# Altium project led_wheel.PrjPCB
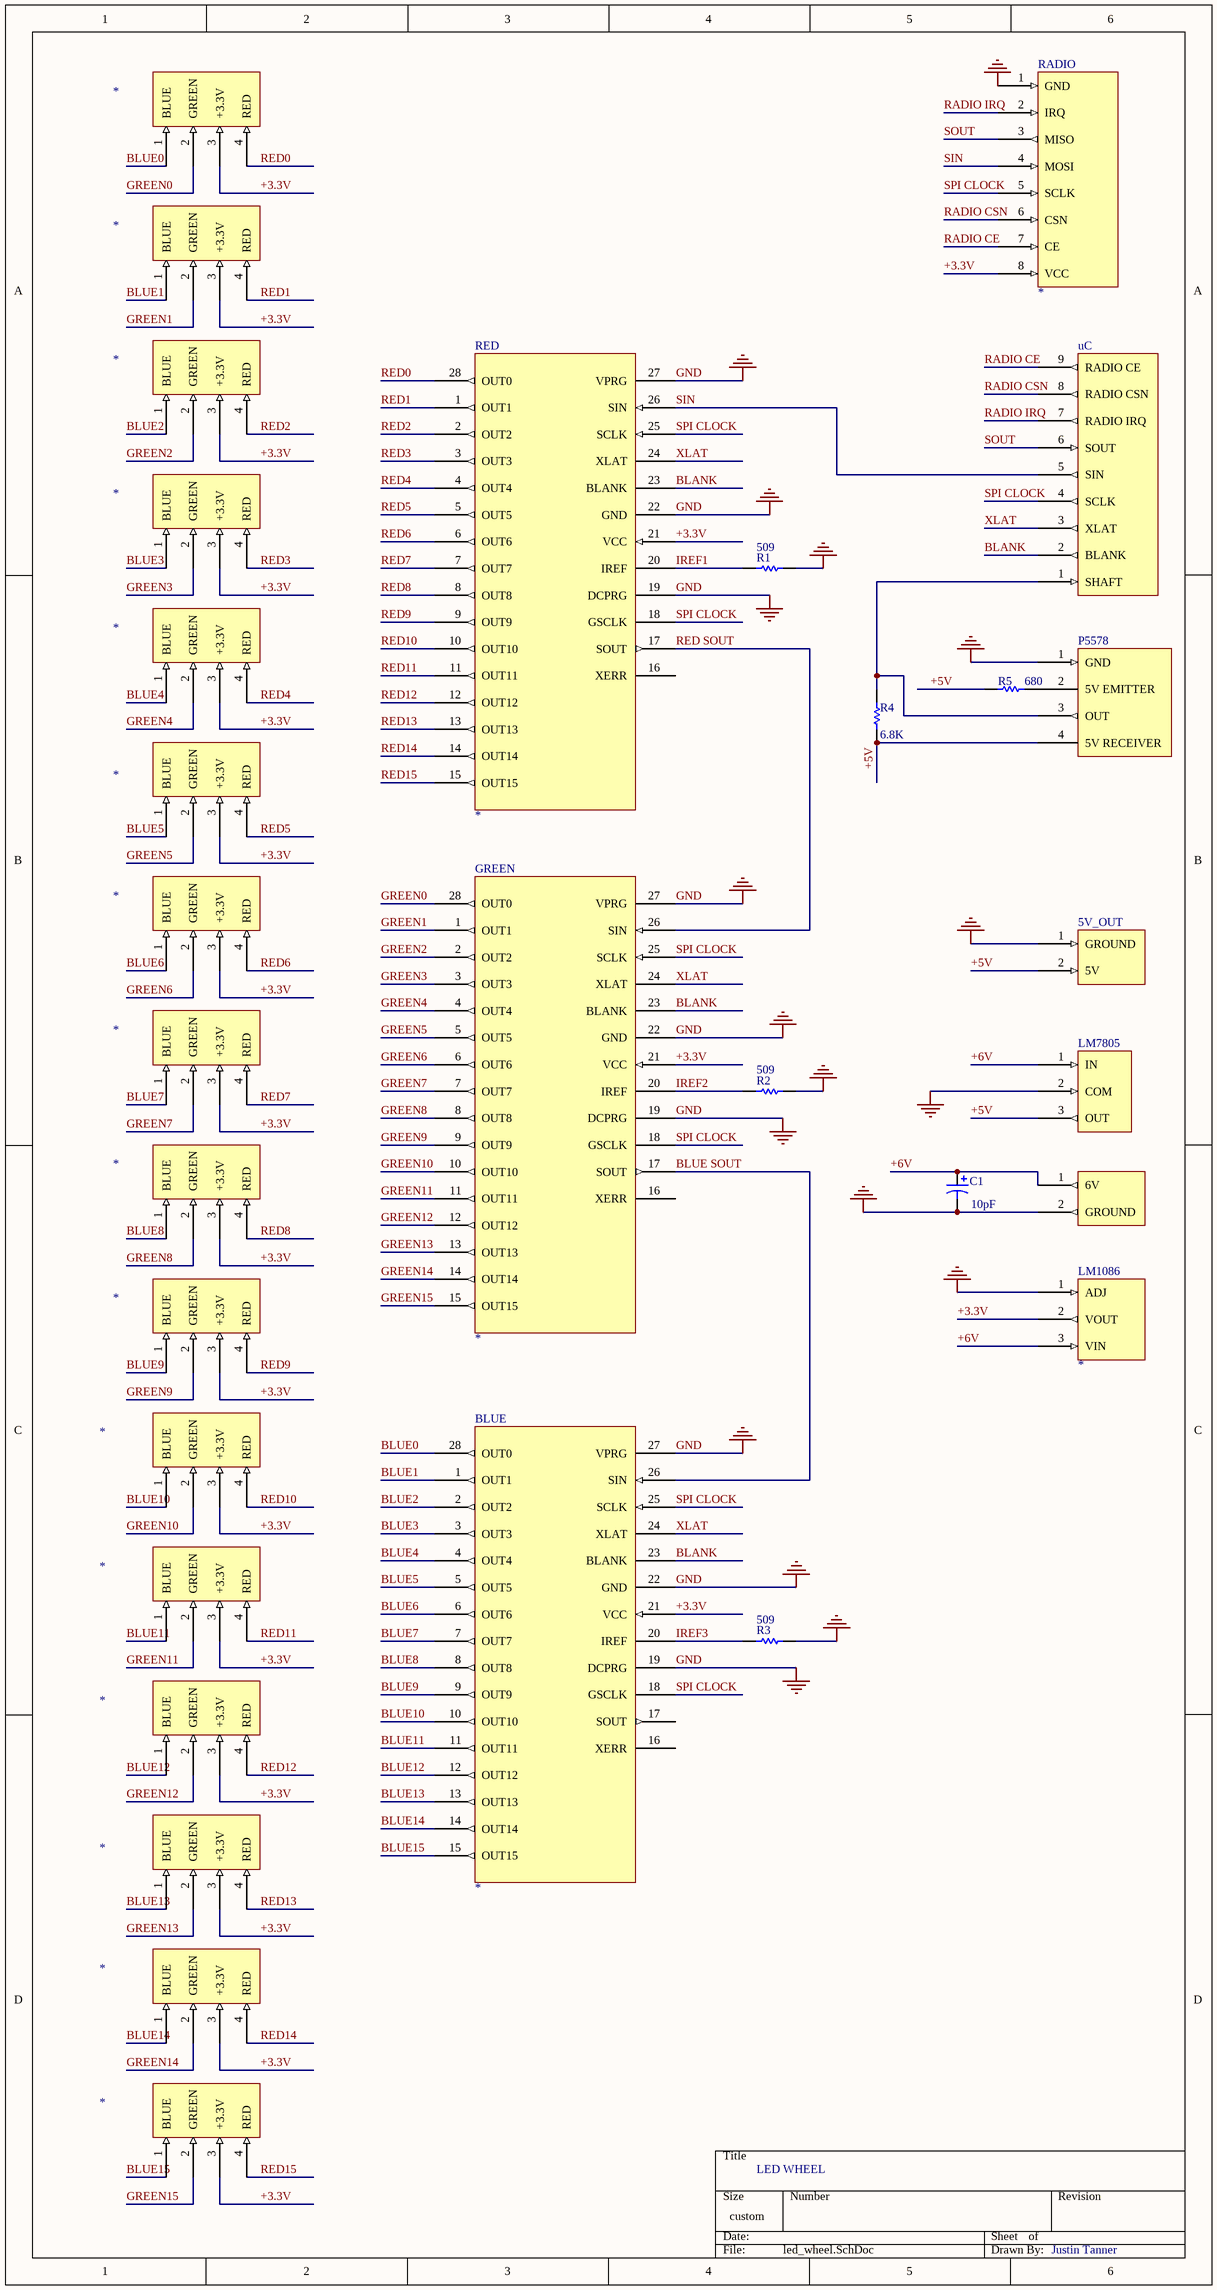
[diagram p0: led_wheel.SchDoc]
1 sheet, 32 parts. Net scope: global (net labels, ports and power ports of the same name join across sheets).
Board files: Breakout.PcbDoc, led_wheel.PcbDoc

## Sheet led_wheel.SchDoc
size 228 x 431 mm

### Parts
0  *  [LED]
1  *  [LED]
2  *  [LED]
3  *  [LED]
4  *  [LED]
5  *  [LED]
5V_OUT  *  [+5V OUT]  (value not drawn)
6  *  [LED]
6V_BATTERIES  *  [+6V BAT]  (value not drawn)
7  *  [LED]
8  *  [LED]
9  *  [LED]
10  *  [LED]
11  *  [LED]
12  *  [LED]
13  *  [LED]
14  *  [LED]
15  *  [LED]
BLUE  *  [PDIP28]
C1  value 10pF  [C10]  (hidden comment: Cap Pol1)
GREEN  *  [PDIP28]
LM1086  *  [LM1086]
LM7805  *  [LM7805]  (value not drawn)
P5578  *  [SHAFT]  (value not drawn)
R1  509  [R509]
R2  value 509  [R509]  (hidden comment: Res1)
R3  value 509  [R509]  (hidden comment: Res1)
R4  value 6.8K  [R6.8K]  (hidden comment: Res1)
R5  value 680  [R680]
RADIO  *  [RADIO]
RED  *  [PDIP28]
uC  *  [TO AT90]  (value not drawn)

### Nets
GND: 5V_OUT.1(GROUND) 6V_BATTERIES.2(GROUND) BLUE.19(DCPRG) BLUE.22(GND) BLUE.27(VPRG) C1.2 GREEN.19(DCPRG) GREEN.22(GND) GREEN.27(VPRG) LM1086.1(ADJ) LM7805.2(COM) P5578.1(GND) R1.2 R2.2 R3.2 RADIO.1(GND) RED.19(DCPRG) RED.22(GND) RED.27(VPRG)
+3.3V: 0.3(+3.3V) 1.3(+3.3V) 2.3(+3.3V) 3.3(+3.3V) 4.3(+3.3V) 5.3(+3.3V) 6.3(+3.3V) 7.3(+3.3V) 8.3(+3.3V) 9.3(+3.3V) 10.3(+3.3V) 11.3(+3.3V) 12.3(+3.3V) 13.3(+3.3V) 14.3(+3.3V) 15.3(+3.3V) BLUE.21(VCC) GREEN.21(VCC) LM1086.2(VOUT) RADIO.8(VCC) RED.21(VCC)
+5V: 5V_OUT.2(5V) LM7805.3(OUT) P5578.4(5V_RECEIVER) R4.1 R5.2
+6V: 6V_BATTERIES.1(6V) C1.1 LM1086.3(VIN) LM7805.1(IN)
BLANK: BLUE.23(BLANK) GREEN.23(BLANK) RED.23(BLANK) uC.2(BLANK)
BLUE0: 0.1(BLUE) BLUE.28(OUT0)
BLUE1: 1.1(BLUE) BLUE.1(OUT1)
BLUE2: 2.1(BLUE) BLUE.2(OUT2)
BLUE3: 3.1(BLUE) BLUE.3(OUT3)
BLUE4: 4.1(BLUE) BLUE.4(OUT4)
BLUE5: 5.1(BLUE) BLUE.5(OUT5)
BLUE6: 6.1(BLUE) BLUE.6(OUT6)
BLUE7: 7.1(BLUE) BLUE.7(OUT7)
BLUE8: 8.1(BLUE) BLUE.8(OUT8)
BLUE9: 9.1(BLUE) BLUE.9(OUT9)
BLUE10: 10.1(BLUE) BLUE.10(OUT10)
BLUE11: 11.1(BLUE) BLUE.11(OUT11)
BLUE12: 12.1(BLUE) BLUE.12(OUT12)
BLUE13: 13.1(BLUE) BLUE.13(OUT13)
BLUE14: 14.1(BLUE) BLUE.14(OUT14)
BLUE15: 15.1(BLUE) BLUE.15(OUT15)
BLUE SOUT: BLUE.26(SIN) GREEN.17(SOUT)
GREEN0: 0.2(GREEN) GREEN.28(OUT0)
GREEN1: 1.2(GREEN) GREEN.1(OUT1)
GREEN2: 2.2(GREEN) GREEN.2(OUT2)
GREEN3: 3.2(GREEN) GREEN.3(OUT3)
GREEN4: 4.2(GREEN) GREEN.4(OUT4)
GREEN5: 5.2(GREEN) GREEN.5(OUT5)
GREEN6: 6.2(GREEN) GREEN.6(OUT6)
GREEN7: 7.2(GREEN) GREEN.7(OUT7)
GREEN8: 8.2(GREEN) GREEN.8(OUT8)
GREEN9: 9.2(GREEN) GREEN.9(OUT9)
GREEN10: 10.2(GREEN) GREEN.10(OUT10)
GREEN11: 11.2(GREEN) GREEN.11(OUT11)
GREEN12: 12.2(GREEN) GREEN.12(OUT12)
GREEN13: 13.2(GREEN) GREEN.13(OUT13)
GREEN14: 14.2(GREEN) GREEN.14(OUT14)
GREEN15: 15.2(GREEN) GREEN.15(OUT15)
IREF1: R1.1 RED.20(IREF)
IREF2: GREEN.20(IREF) R2.1
IREF3: BLUE.20(IREF) R3.1
RADIO CE: RADIO.7(CE) uC.9(RADIO_CE)
RADIO CSN: RADIO.6(CSN) uC.8(RADIO_CSN)
RADIO IRQ: RADIO.2(IRQ) uC.7(RADIO_IRQ)
RED0: 0.4(RED) RED.28(OUT0)
RED1: 1.4(RED) RED.1(OUT1)
RED2: 2.4(RED) RED.2(OUT2)
RED3: 3.4(RED) RED.3(OUT3)
RED4: 4.4(RED) RED.4(OUT4)
RED5: 5.4(RED) RED.5(OUT5)
RED6: 6.4(RED) RED.6(OUT6)
RED7: 7.4(RED) RED.7(OUT7)
RED8: 8.4(RED) RED.8(OUT8)
RED9: 9.4(RED) RED.9(OUT9)
RED10: 10.4(RED) RED.10(OUT10)
RED11: 11.4(RED) RED.11(OUT11)
RED12: 12.4(RED) RED.12(OUT12)
RED13: 13.4(RED) RED.13(OUT13)
RED14: 14.4(RED) RED.14(OUT14)
RED15: 15.4(RED) RED.15(OUT15)
RED SOUT: GREEN.26(SIN) RED.17(SOUT)
SIN: RADIO.4(MOSI) RED.26(SIN) uC.5(SIN)
SOUT: RADIO.3(MISO) uC.6(SOUT)
SPI CLOCK: BLUE.18(GSCLK) BLUE.25(SCLK) GREEN.18(GSCLK) GREEN.25(SCLK) RADIO.5(SCLK) RED.18(GSCLK) RED.25(SCLK) uC.4(SCLK)
XLAT: BLUE.24(XLAT) GREEN.24(XLAT) RED.24(XLAT) uC.3(XLAT)
NetP5578_2: P5578.2(5V_EMITTER) R5.1
NetP5578_3: P5578.3(OUT) R4.2 uC.1(SHAFT)

Not connected (* = marked no-connect by the designer): BLUE 16(XERR) 17(SOUT); GREEN 16(XERR); RED 16(XERR)

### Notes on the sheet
- LED WHEEL
- Justin Tanner

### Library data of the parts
0-15 = LED
5V_OUT = 5V_OUT
6V_BATTERIES = 6V_BATTERIES
BLUE GREEN RED = TLC5940NT
C1 = Cap Pol2: Polarized Capacitor (Axial)
LM1086 = LM1086
LM7805 = LM7805
P5578 = P5578
R1-R5 = Res1: Resistor
RADIO = RADIO
uC = TO_AT90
